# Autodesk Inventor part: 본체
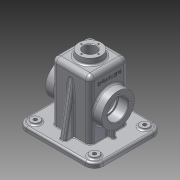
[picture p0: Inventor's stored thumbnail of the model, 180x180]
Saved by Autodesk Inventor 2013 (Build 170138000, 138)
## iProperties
Created: 2016-01
Part Number: 본체
Material: 알루미늄 6061
Document SubType Name: Modeling
Designer: User
Density: 2.71 g/cm^3
Mass: 803.695 g
Surface Area: 915.697 cm^2
Volume: 296.566 cm^3
Author: User
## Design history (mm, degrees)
sketch "스케치1"
  geometry: L1 (-60, 52.5)-(60, 52.5); L2 (60, 52.5)-(60, -52.5); L3 (60, -52.5)-(-60, -52.5); L4 (-60, -52.5)-(-60, 52.5); L5 (-60, 52.5)-(60, -52.5); L6 (60, 52.5)-(-60, -52.5); 1 further point
  constraints: 12 end point, 2 midpoint, 2 parallel, 1 horizontal, 1 perpendicular
  dimensions: "d0" = 120 distance of L1.start L1.end; "d2" = 105 distance of L1.end L2.end
extrude "돌출1" new body sketch "스케치1" distance "d3" = 2; taper "d4" = 0 deg
sketch "스케치2"
  geometry: L1 (-65, 57.5)-(65, 57.5); L2 (65, 57.5)-(65, -57.5); L3 (65, -57.5)-(-65, -57.5); L4 (-65, -57.5)-(-65, 57.5); L5 (-65, 57.5)-(65, -57.5); L6 (65, 57.5)-(-65, -57.5); 1 further point
  constraints: 12 end point, 2 midpoint, 2 parallel, 1 horizontal, 1 perpendicular
  dimensions: "d5" = 130 distance of L1.start L1.end; "d7" = 115 distance of L1.end L2.end
extrude "돌출2" join sketch "스케치2" distance "d8" = 8; taper "d9" = 0 deg
sketch "스케치3"
  geometry: L1 (-32.5, 32.5)-(32.5, 32.5); L2 (32.5, 32.5)-(32.5, -32.5); L3 (32.5, -32.5)-(-32.5, -32.5); L4 (-32.5, -32.5)-(-32.5, 32.5); L5 (-32.5, 32.5)-(32.5, -32.5); L6 (32.5, 32.5)-(-32.5, -32.5); 3 further points
  constraints: 12 end point, 3 midpoint, 2 parallel, 1 coincident, 1 horizontal, 1 perpendicular
  dimensions: "d12" = 65 distance of L1.start L1.end; "d14" = 65 distance of L1.end L2.end
extrude "돌출3" join sketch "스케치3" distance "d15" = 100; taper "d16" = 0 deg
node "작업 평면1"
sketch "스케치5"
  geometry: L1 (-20, -10)-(85, -10) reference; C1 r 27.5 at (32.5, 45); 1 further point
  constraints: 1 centre point, 1 vertical alignment
  dimensions: "d21" = 55 diameter of C1; "d23" = 55 distance from line of C1.centre L1
extrude "돌출4" join sketch "스케치5" stored distance "d24" = 95; taper "d25" = 0 deg
hole "구멍1" diameter "d28" = 35; stored, may be unused: countersink angle "d32" = 90 deg, drill point angle "d34" = 0 deg; dims "d26" = 10, "d27" = 10, "d29" = 6, "d30" = 4, "d31" = 2, "d33" = 17
sketch "스케치6"
  geometry: L1 (-27.5, 27.5)-(27.5, 27.5); L2 (27.5, 27.5)-(27.5, -27.5); L3 (27.5, -27.5)-(-27.5, -27.5); L4 (-27.5, -27.5)-(-27.5, 27.5); L5 (-27.5, 27.5)-(27.5, -27.5); L6 (27.5, 27.5)-(-27.5, -27.5); 1 further point
  constraints: 12 end point, 2 midpoint, 2 parallel, 1 horizontal, 1 perpendicular
  dimensions: "d35" = 55 distance of L1.start L1.end; "d37" = 55 distance of L1.end L2.end
extrude "돌출5" cut sketch "스케치6" distance "d38" = 105; taper "d39" = 0 deg
node "작업 평면2"
sketch "스케치7"
  geometry: C1 r 20 at (0, 0); 1 further point
  constraints: 1 centre point, 1 coincident
  dimensions: "d41" = 40 diameter of C1
extrude "돌출6" join sketch "스케치7" stored distance "d43" = 105; taper "d44" = 0 deg
hole "구멍2" diameter "d47" = 21; stored, may be unused: countersink angle "d51" = 90 deg, drill point angle "d53" = 0 deg; dims "d45" = 10, "d46" = 10, "d48" = 6, "d49" = 4, "d50" = 2, "d52" = 17
fillet "모깎기1" dims "d54" = 15
sketch "스케치8"
  geometry: C1 r 7.5 at (-50, 42.5); C2 r 7.5 at (50, 42.5); C3 r 7.5 at (50, -42.5); C4 r 7.5 at (-50, -42.5); A1 r 15 centre (50, 42.5) between (65, 42.5) and (50, 57.5) reference; A2 r 15 centre (-50, 42.5) between (-50, 57.5) and (-65, 42.5) reference; A3 r 15 centre (-50, -42.5) between (-65, -42.5) and (-50, -57.5) reference; A4 r 15 centre (50, -42.5) between (50, -57.5) and (65, -42.5) reference; 1 further point
  constraints: 4 centre point, 4 coincident
  dimensions: "d55" = 15 diameter of C1; "d56" = 15 diameter of C2; "d57" = 15 diameter of C3; "d58" = 15 diameter of C4
extrude "돌출7" join sketch "스케치8" distance "d59" = 3; taper "d60" = 0 deg
hole "구멍3" diameter "d63" = 30; stored, may be unused: countersink angle "d67" = 90 deg, drill point angle "d69" = 0 deg; dims "d61" = 10, "d62" = 10, "d64" = 6, "d65" = 4, "d66" = 2, "d68" = 17
sketch "스케치9"
  geometry: C1 r 10.5 at (0, 0) reference; 1 further point
  constraints: 1 vertical alignment
  dimensions: "d70" = 14.5 distance of C1.centre point (0, 14.5)
hole "구멍4" sketch "스케치9" at (0, 14.5) diameter "d71" = 2.459; stored, may be unused: countersink angle "d75" = 90 deg, drill point angle "d77" = 118 deg; dims "d72" = 7, "d73" = 4, "d74" = 2, "d76" = 9
sketch "스케치10"
  geometry: C1 r 17.5 at (0, 0) reference; 2 further points
  constraints: 1 vertical alignment
  dimensions: "d81" = 21 distance of C1.centre point (0, 21)
hole "구멍5" sketch "스케치10" at (0, 21) diameter "d82" = 3.242; stored, may be unused: countersink angle "d86" = 90 deg, drill point angle "d88" = 118 deg; dims "d83" = 8, "d84" = 4, "d85" = 2, "d87" = 10
fillet "모깎기2" dims "d92" = 10
node "작업 평면3"
sketch "스케치11"
  geometry: L1 (0, 0)-(65, 0) reference; L2 (0, 0)-(0, 100) reference; L3 (65, 100)-(0, 100) reference; L4 (65, 0)-(65, 100) reference; L5 (-25, 0)-(-10, 0) reference; L6 (75, 0)-(90, 0) reference; L7 (0, 85.069)-(-15, 0); L8 (-25, -8)-(-25, 0) reference; L9 (65, 85.069)-(80, 0); L10 (90, 0)-(90, -8) reference; L11 (0, 85.069)-(0, 0); L12 (-15, 0)-(0, 0); L13 (65, 0)-(80, 0); L14 (65, 0)-(65, 85.069); C1 r 27.5 at (32.5, 45) reference; 1 further point
  constraints: 12 end point, 4 point on line, 2 collinear, 1 parallel, 1 perpendicular
  dimensions: "d94" = 10 deg angle of L7 L8; "d95" = 10 deg angle of L9 L10; "d96" = 10 distance from line of L10 L9.end; "d97" = 10 distance from line of L8 L7.end
extrude "돌출8" join sketch "스케치11" stored distance "d98" = 10; taper "d99" = 0 deg
fillet "모깎기4" dims "d101" = 0.3
chamfer "모따기1" distance "d102" = 1; stored, may be unused: second distance "d103" = 2, angle "d104" = 45 deg
chamfer "모따기2" distance "d105" = 1; stored, may be unused: second distance "d106" = 2, angle "d107" = 45 deg
hole "구멍6" diameter "d110" = 6; stored, may be unused: countersink angle "d114" = 90 deg, drill point angle "d116" = 118 deg; dims "d108" = 10, "d109" = 10, "d111" = 6, "d112" = 4, "d113" = 2, "d115" = 10
hole "구멍7" diameter "d119" = 6; stored, may be unused: countersink angle "d123" = 90 deg, drill point angle "d125" = 118 deg; dims "d117" = 10, "d118" = 10, "d120" = 6, "d121" = 4, "d122" = 2, "d124" = 10
hole "구멍8" diameter "d128" = 6; stored, may be unused: countersink angle "d132" = 90 deg, drill point angle "d134" = 118 deg; dims "d126" = 10, "d127" = 10, "d129" = 6, "d130" = 4, "d131" = 2, "d133" = 10
hole "구멍9" diameter "d137" = 6; stored, may be unused: countersink angle "d141" = 90 deg, drill point angle "d143" = 118 deg; dims "d135" = 10, "d136" = 10, "d138" = 6, "d139" = 4, "d140" = 2, "d142" = 10
fillet "모깎기5" dims "d144" = 8
chamfer "모따기3" distance "d146" = 1; stored, may be unused: second distance "d147" = 2, angle "d148" = 45 deg
sketch "스케치13"
  geometry: L1 (-27.5, 3)-(-42.5, 3); L2 (-42.5, 3)-(-42.5, -3); L3 (-42.5, -3)-(-27.5, -3); L4 (-27.5, -3)-(-27.5, 3); L5 (-27.5, -27.5)-(27.5, -27.5) reference; L6 (-27.5, 27.5)-(-27.5, -27.5) reference; L7 (27.5, -27.5)-(27.5, 27.5) reference; L8 (42.5, 3)-(27.5, 3); L9 (27.5, 3)-(27.5, -3); L10 (27.5, -3)-(42.5, -3); L11 (42.5, -3)-(42.5, 3); 4 further points
  constraints: 16 end point, 4 midpoint, 4 parallel, 2 coincident, 2 horizontal, 2 perpendicular, 1 horizontal alignment
  dimensions: "d154" = 6 distance of L1.end L2.end; "d156" = 15 distance of L2.end L3.end; "d157" = 15 distance of L9.end L10.end; "d158" = 6 distance of L10.end L8.start
extrude "돌출10" join sketch "스케치13" stored distance "d159" = 6; taper "d160" = 0 deg
fillet "모깎기7" dims "d161" = 3
fillet "모깎기8" dims "d162" = 8
fillet "모깎기9" dims "d163" = 3
fillet "모깎기10" dims "d164" = 3
fillet "모깎기13" dims "d167" = 3
sketch "스케치14"
  geometry: L1 (-8, 0)-(-8, -92) reference; L2 (4.5, 18)-(44.5, 18) reference; 3 further points
  constraints: 1 other
  dimensions: "d169" = 32.5 distance from line of L1 point (24.5, -8); "d170" = 26 distance from line of point (24.5, -8) L2
feature "엠보싱1" sketch "스케치14" dims "d171" = 0.5, "d172" = 0
fillet "모깎기15" dims "d173" = 3
fillet "모깎기16" dims "d174" = 3
fillet "모깎기17" dims "d175" = 3
fillet "모깎기18" dims "d176" = 3
fillet "모깎기19" dims "d177" = 1
fillet "모깎기20" dims "d178" = 3
fillet "모깎기21" dims "d179" = 3
node "작업 평면4"
feature "면 기울기1" dims angle "d181" = 5 deg
fillet "모깎기22" dims "d182" = 3
node "솔리드1"
mirror "대칭1"
pattern_circular "원형 패턴1" dims angle "d79" = 360 deg
pattern_circular "원형 패턴2" dims angle "d90" = 360 deg
mirror "대칭2"
node "투영된 루프1"
other parameters: "d20" = -32.5, "d93" = -32.5, "d180" = 0
